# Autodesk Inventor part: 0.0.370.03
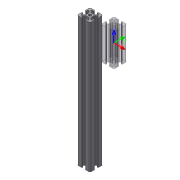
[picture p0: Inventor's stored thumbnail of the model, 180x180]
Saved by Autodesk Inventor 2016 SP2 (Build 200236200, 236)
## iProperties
Created: 2017-10
Part Number: 0.0.370.03
Material: Aluminium - 6061
Vendor: Item
Document SubType Name: Modeling
Designer: CAD Team Handzik
Density: 2.71 g/cm^3
Appearance: Aluminium - flach
Category: natur
Company: CAD Team Handzik
Title: Profil 5 20x20
Subject: Muster für iPart Modul
Author: CAD Team Handzik
MT_KOPF: =<CPR_ZEICHNR> - <CPR_SHORT>
LANG: 200,000 mm
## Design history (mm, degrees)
derived "0.0.370.03.ipt"
feature "Volumenkörper3::0.0.370.03.ipt"
tag "Bezeichnung1"
node "Volumenkörper1"
other parameters: "d11" = 0, "LANG" = 200
